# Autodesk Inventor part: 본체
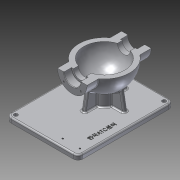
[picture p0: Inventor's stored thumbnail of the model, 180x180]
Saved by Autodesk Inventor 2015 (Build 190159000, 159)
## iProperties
Created: 2015-12
Part Number: 본체
Material: 알루미늄 6061
Document SubType Name: Modeling
Designer: mduedu
Density: 2.71 g/cm^3
Appearance: 알루미늄 - 평지
Author: mduedu
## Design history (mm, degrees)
sketch "스케치1"
  geometry: L1 (-53, 0)-(53, 0); A1 r 53 centre (0, 0) between (53, 0) and (-53, 0); 2 further points
  constraints: 2 coincident, 2 end point, 2 point on circle, 1 centre point, 1 horizontal, 1 midpoint
  dimensions: "d0" = 53 radius of A1
revolve "회전1" sketch "스케치1" stored, may be unused: angle "d2" = 90 deg
feature "쉘1" dims "d11" = 10
node "작업 평면1"
sketch "스케치2"
  geometry: C1 r 31 at (0, 0); 1 further point
  constraints: 1 centre point, 1 coincident
  dimensions: "d4" = 62 diameter of C1
extrude "돌출1" join sketch "스케치2" stored distance "d5" = 10; taper "d6" = 0 deg
hole "구멍1" diameter "d14" = 35; stored, may be unused: countersink angle "d18" = 90 deg, drill point angle "d20" = 0 deg; dims "d12" = 10, "d13" = 10, "d15" = 6, "d16" = 4, "d17" = 2, "d19" = 16
hole "구멍2" diameter "d23" = 27; stored, may be unused: countersink angle "d27" = 90 deg, drill point angle "d29" = 0 deg; dims "d21" = 10, "d22" = 10, "d24" = 6, "d25" = 4, "d26" = 2, "d28" = 16
fillet "모깎기1" dims "d30" = 0.3
chamfer "모따기1" distance "d40" = 1; stored, may be unused: second distance "d41" = 2, angle "d42" = 45 deg
sketch "스케치4"
  geometry: L1 (0, 0)-(0, -25); L2 (0, 0)-(-17.678, -17.678); A1 r 25 centre (0, 0) between (-17.678, -17.678) and (0, -25); 1 further point
  constraints: 4 end point, 2 point on circle, 1 centre point, 1 coincident, 1 vertical
  dimensions: "d43" = 50 diameter of A1; "d47" = 45 deg angle of L1 L2
hole "구멍4" sketch "스케치4" at (-17.678, -17.678) diameter "d49" = 3.242; stored, may be unused: countersink angle "d53" = 90 deg, drill point angle "d55" = 118 deg; dims "d50" = 11, "d51" = 4, "d52" = 2, "d54" = 13
node "작업 평면3"
sketch "스케치6" dims "d22" = 10
  geometry: L1 (-70, -75)-(130, -75); L2 (130, -75)-(130, 75); L3 (130, 75)-(-70, 75); L4 (-70, 75)-(-70, -75); 2 further points
  constraints: 8 end point, 2 parallel, 1 coincident, 1 horizontal, 1 perpendicular
  dimensions: "d158" = 200 distance of L3.end L2.end; "d159" = 150 distance of L2.end L1.end; "d162" = 75 distance from line of L1 point (0, 0); "d163" = 70 distance from line of L4 point (0, 0)
extrude "돌출3" join sketch "스케치6" distance "d80" = 10; taper "d81" = 0 deg
sketch "스케치7"
  geometry: C1 r 20 at (0, 0); 2 further points
  constraints: 2 coincident, 1 centre point
  dimensions: "d82" = 40 diameter of C1
extrude "돌출4" join sketch "스케치7" stored distance "d84" = 10; taper "d85" = 0 deg
sketch "스케치8"
  geometry: 3 further points
  constraints: 2 coincident
hole "구멍6" sketch "스케치8" at (0, 0) diameter "d86" = 20; stored, may be unused: countersink angle "d90" = 90 deg, drill point angle "d92" = 118 deg; dims "d87" = 7, "d88" = 40, "d89" = 5, "d91" = 10
fillet "모깎기2" dims "d93" = 0.3
sketch "스케치9"
  geometry: L1 (-45, -75)-(-38.245, -36.692); L2 (70, -75)-(-130, -75) reference; A1 r 53 centre (0, 0) between (42.988, 31) and (42.988, -31) reference; 1 further point
  constraints: 2 end point, 1 coincident, 1 point on circle, 1 point on line
  dimensions: "d94" = 45 horizontal distance of L1.start point (0, 0); "d160" = 80 deg angle of L2 L1
feature "리브1" sketch "스케치9" dims "d96" = 1, "d97" = 8, "d98" = 0, "d99" = 0, "d100" = 1, "d101" = 1
fillet "모깎기3" dims "d120" = 3
fillet "모깎기4" dims "d121" = 3, "d122" = 3
fillet "모깎기5" dims "d123" = 3
sketch "스케치12"
  geometry: L1 (0, 100)-(0, -100); L2 (0, 100)-(100, 100); L3 (100, 100)-(100, -100); L4 (100, -100)-(0, -100); 2 further points
  constraints: 8 end point, 3 perpendicular, 1 coincident, 1 midpoint, 1 vertical
  dimensions: "d127" = 200 distance of L2.end L3.end; "d129" = 100 distance between parallel lines of L1 L3
extrude "돌출5" cut sketch "스케치12" stored distance "d130" = 10; taper "d131" = 0 deg
fillet "모깎기10" dims "d164" = 10
fillet "모깎기11" dims "d165" = 3
sketch "스케치15"
  geometry: C1 r 4 at (-120, 65); C2 r 4 at (60, 65); C3 r 4 at (60, -65); A1 r 10 centre (-120, 65) between (-120, 75) and (-130, 65) reference; A2 r 10 centre (60, 65) between (70, 65) and (60, 75) reference; A3 r 10 centre (60, -65) between (60, -75) and (70, -65) reference; 1 further point
  constraints: 3 centre point, 3 coincident, 2 equal radius
  dimensions: "d166" = 8 diameter of C1
extrude "돌출8" cut sketch "스케치15" stored distance "d167" = 10; taper "d168" = 0 deg
sketch "스케치16"
  geometry: L1 (-130, 65)-(-130, -65) reference; L2 (-120, -75)-(60, -75) reference; 2 further points
  constraints: 1 other
  dimensions: "d169" = 70 distance from line of point (-60, -55) L1; "d170" = 20 distance from line of point (-60, -55) L2
feature "엠보싱2" sketch "스케치16" dims "d171" = 0.5, "d172" = 0
sketch "스케치17"
  geometry: L1 (-120, 75)-(60, 75) reference; L2 (-130, -65)-(-130, 65) reference; 2 further points
  constraints: 1 vertical alignment
  dimensions: "d180" = 12 distance from line of L1 point (-114, 63); "d181" = 16 distance from line of point (-114, 63) L2; "d182" = 36 distance of point (-114, 27) point (-114, 63)
hole "구멍9" sketch "스케치17" at (-114, 63), (-114, 27) diameter "d173" = 3.242; stored, may be unused: countersink angle "d177" = 90 deg, drill point angle "d179" = 0 deg; dims "d174" = 6, "d175" = 4, "d176" = 2, "d178" = 8
node "솔리드1"
mirror "대칭1"
mirror "대칭2"
pattern_circular "원형 패턴1" dims angle "d57" = 360 deg
mirror "대칭3"
pattern_circular "원형 패턴3" dims angle "d103" = 360 deg
other parameters: "d3" = 67, "d77" = -85
